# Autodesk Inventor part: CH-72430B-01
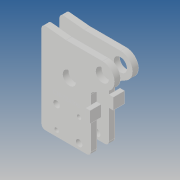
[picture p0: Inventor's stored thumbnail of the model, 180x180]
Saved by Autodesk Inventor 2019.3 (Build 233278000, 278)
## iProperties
Created: 2012-10
Part Number: CH-72430B-01
Material: Ogólny
Document SubType Name: Modeling
Designer: CADENGINEERING4
Density: 1 g/cm^3
Appearance: Domyślna
Author: CADENGINEERING4
Revision Number: ÈÎºÎ
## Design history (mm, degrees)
feature "Í¹Ì¨-À­Éì1[1]"
feature "Í¹Ì¨-À­Éì1[2]"
node "Bryła1"
node "Bryła22"
node "Bryła23"
